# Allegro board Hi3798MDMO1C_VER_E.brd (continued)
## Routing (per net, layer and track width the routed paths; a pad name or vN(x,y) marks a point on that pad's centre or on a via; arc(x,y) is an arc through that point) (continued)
VDD_AUDIO: length 12.2
  TOP w0.254: U5.9 100.93,67.09 R48.1 C158.1 101.45,64.66 C320.1 101.41,63.4 R179.2 100.57,63.37 100.01,63.93 R66.2
ADAC_VOUTL: length 29.9
  TOP w0.254: C350.2 97.18,61.51 96.88,61.81 R50.1 96.47,61.69 96.03,61.25 78.02,61.25 76.21,59.43 76.21,54.48 75.48,53.75 74.9,53.75 U1.B22
ADAC_VOUTR: length 20.9
  TOP w0.254: C351.1 87.99,64.67 R183.1 87.9,63.7 83.27,63.7 82.68,63.11 78.16,63.11 75.17,60.12 75.17,55.78 U1.A22
AUDIO_L: length 9.1
  BOTTOM w0.254: J34.2 100.95,76.83 99.83,75.71 C339.1 99.83,70.7 99.83,70.7 R72.2
AUDIO_R: length 10.8
  BOTTOM w0.254: R74.1 92.58,70.06 92.58,71.11 ; 92.58,71.11 C140.1 ; 92.58,71.11 92.58,75.6 91.35,76.82 89.33,76.82 89.32,76.83 J34.1
CORE_CTRL: length 9.8
  TOP w0.127: U1.H22 74.42,49.6 74.99,50.17 76.69,50.17 77.43,50.92 79.51,50.92 81.14,52.55 81.14,53.44 80.94,53.65 R23.2
CPU_CTRL: length 10.2
  TOP w0.127: U1.H23 75.36,49.29 76.56,49.29 77.5,50.23 80.38,50.23 82.04,51.9 82.04,54.07 R21.2
CVBS: length 49.3
  TOP w0.254: C80.1 108.78,71.08 L6.1 107.89,71.1 C79.1 R9.1 106.98,69.54 106.81,69.36 106.81,64.02 102.89,60.1 78.63,60.1 77.35,58.82 77.35,53.95 75.24,51.83 U1.E23
CVBS_OUT: length 14.4
  TOP w0.254: v1(114.78,70.38) 113.81,70.38 D9.3 112.29,71.9 C17.1 C80.2 108.78,71.9 L6.2
  BOTTOM w0.254: J34.3 117.84,73.44 v1(114.78,70.38)
DDR_ADDR0: length 98
  TOP w0.127: U1.AC14 68.02,37.07 67.94,36.99 67.94,22.81 59.68,14.55 30.21,14.55 20.46,24.3 20.46,42.65 25.81,48 v1(25.94,48) RN2.1
  BOTTOM w0.127: RN2.1 v1(25.94,48)
DDR_ADDR0_A: length 18.5
  TOP w0.127: U3.N3 41.01,47.56 41.42,47.96 41.42,50.49 40.19,51.71 31.91,51.71 28.2,48 RN2.8
DDR_ADDR0_B: length 24.2
  TOP w0.127: U6.N3 41.01,31.25 41.42,31.66 41.42,33.98 40.06,35.34 v1(40.06,35.42)
  BOTTOM w0.127: v1(40.06,35.42) 39.97,35.42 39.67,35.72 39.67,36.85 35.26,41.26 35.26,42.75 29.52,48.49 28.77,48.49 28.29,48 RN11.1
DDR_ADDR1: length 66.5
  TOP w0.127: v1(26.37,32.98) 26.45,33.07 26.5,33.07 26.57,33.15 RN4.3 ; U1.Y10 v2(65.22,40.23)
  BOTTOM w0.127: v2(65.22,40.23) 65.06,40.23 64.57,39.75 64.57,31.72 52.6,19.75 30.75,19.75 24.31,26.19 24.31,30.96 26.34,32.98 v1(26.37,32.98) 26.53,33.15 RN4.3
DDR_ADDR1_A: length 17.3
  TOP w0.127: U3.P7 40.21,44.01 39.83,43.64 39.83,43.36 39.5,43.03 39.2,43.03 38.97,42.8 38.97,42.27 38.76,42.06 37.54,42.06 28.62,33.15 RN4.6
DDR_ADDR1_B: length 17.6
  TOP w0.127: v1(36.05,25.73) 38.61,25.73 38.97,26.09 38.97,26.36 39.17,26.57 39.55,26.57 39.86,26.87 39.86,27.23 40.21,27.58 U6.P7
  BOTTOM w0.127: RN13.3 28.25,33.15 30.84,30.56 30.84,28.81 33.49,26.16 35.62,26.16 v1(36.05,25.73)
DDR_ADDR2: length 95.4
  TOP w0.127: U1.W14 v2(68.42,40.24) ; RN1.4 v1(26.47,42.67)
  BOTTOM w0.127: v2(68.42,40.24) 68.42,40.04 68.83,39.64 68.83,27.93 55.9,15 28.41,15 19.56,23.85 19.56,37.57 24.67,42.67 v1(26.47,42.67) RN1.4
DDR_ADDR2_A: length 14.4
  TOP w0.127: U3.P3 39.87,47.09 37.3,47.09 36.89,47.5 33.57,47.5 28.75,42.67 RN1.5
DDR_ADDR2_B: length 18.7
  TOP w0.127: U6.P3 39.87,30.68 38.3,30.68 37.32,31.66 37.32,31.68 36.55,32.45 v1(36.55,32.63)
  BOTTOM w0.127: v1(36.55,32.63) 36.34,32.84 36.34,34.43 31.12,39.64 31.12,40.48 28.93,42.67 RN9.4
DDR_ADDR3: length 96.5
  TOP w0.127: U1.AB14 68.02,37.92 67.68,37.58 67.68,37.29 67.69,37.28 67.69,23.09 59.53,14.93 30.37,14.93 20.84,24.46 20.84,42.49 25.85,47.5 v1(26.47,47.5) RN2.2
  BOTTOM w0.127: RN2.2 v1(26.47,47.5)
DDR_ADDR3_A: length 17
  TOP w0.127: U3.N2 41.01,48.45 40.61,48.85 40.61,50.63 39.91,51.33 32.06,51.33 28.61,47.88 28.61,47.7 28.4,47.5 RN2.7
DDR_ADDR3_B: length 22.7
  TOP w0.127: U6.N2 41.01,32.02 40.62,32.41 40.62,34.17 v1(39.33,35.46)
  BOTTOM w0.127: v1(39.33,35.46) 39.33,36.66 34.88,41.11 34.88,42.59 29.36,48.11 28.84,48.11 28.61,47.88 28.61,47.62 28.48,47.5 RN11.2
DDR_ADDR4: length 64.4
  TOP w0.127: U1.W10 64.82,40.63 v2(64.42,40.24) ; RN4.4 26.85,32.64 26.42,32.2 v1(26.42,32.2)
  BOTTOM w0.127: RN4.4 26.83,32.64 26.42,32.23 v1(26.42,32.2) 26.21,32.2 26.04,32.03 26.02,32.03 24.69,30.7 24.69,26.35 30.91,20.13 52.44,20.13 64.27,31.96 64.27,40.08 v2(64.42,40.24)
DDR_ADDR4_A: length 17.2
  TOP w0.127: RN4.5 28.66,32.64 37.7,41.68 39.56,41.68 39.81,41.93 39.81,42.83 40.21,43.23 U3.P8
DDR_ADDR4_B: length 17.4
  TOP w0.127: v1(35.29,25.73) 35.75,25.26 36.39,25.26 36.5,25.36 39.01,25.36 39.03,25.34 39.36,25.34 39.75,25.74 39.75,26.08 39.75,26.08 39.75,26.26 40.21,26.72 U6.P8
  BOTTOM w0.127: v1(35.29,25.73) 33.38,25.73 30.46,28.65 30.46,30.42 28.24,32.64 RN13.4
DDR_ADDR5: length 107.3
  TOP w0.127: RN2.3 v1(25.94,46.99) ; U1.Y16 v2(70.02,40.23)
  BOTTOM w0.127: RN2.3 v1(25.94,46.99) 24.87,46.99 17.92,40.04 17.92,21.4 26,13.32 56.64,13.32 70.42,27.1 70.42,39.65 70.02,40.04 v2(70.02,40.23)
DDR_ADDR5_A: length 15.1
  TOP w0.127: RN2.6 28.99,46.99 32.39,50.39 39.26,50.39 39.81,49.84 39.81,48.63 U3.P2
DDR_ADDR5_B: length 20.6
  TOP w0.127: U6.P2 39.81,32.23 39.81,33.46 39.33,33.95 v2(39.33,34.39)
  BOTTOM w0.127: v2(39.33,34.39) 38.64,35.08 38.64,36.16 34.02,40.77 34.02,41.96 28.99,46.99 RN11.3
DDR_ADDR6: length 70.3
  TOP w0.102: 65.1,37.01 65.09,37.03 65.09,37.89 65.15,37.95 65.15,38.7 U1.AA10
  TOP w0.127: 65.1,37.01 65.1,26.14 56.86,17.89 33.14,17.89 24.65,26.38 24.65,32.24 26.16,33.75 v1(26.21,33.75) 26.31,33.65 RN4.2
  BOTTOM w0.127: v1(26.21,33.75) 26.32,33.64 27.06,33.64 RN4.2
DDR_ADDR6_A: length 15.6
  TOP w0.127: U3.R8 39.12,43.43 38.7,43.01 37.29,43.01 28.56,34.28 28.56,33.78 28.43,33.65 RN4.7
DDR_ADDR6_B: length 15.4
  TOP w0.127: v1(35.13,27.02) 35.55,26.61 36.21,26.61 36.28,26.67 38.74,26.67 39.1,27.02 U6.R8
  BOTTOM w0.127: RN13.2 28.96,33.65 31.69,30.92 31.69,29.22 33.89,27.02 v1(35.13,27.02)
DDR_ADDR7: length 103.8
  TOP w0.127: RN2.4 v1(26.47,46.48) ; U1.AA16 v2(70.02,39.43)
  BOTTOM w0.127: v2(70.02,39.43) 70.02,27.25 56.48,13.71 26.15,13.71 18.3,21.56 18.3,39.86 24.92,46.48 v1(26.47,46.48) RN2.4
DDR_ADDR7_A: length 13.9
  TOP w0.127: U3.R2 39.41,48.45 39,48.87 39,49.39 38.37,50.01 32.57,50.01 29.04,46.48 RN2.5
DDR_ADDR7_B: length 19.8
  TOP w0.127: v2(38.56,34.43) 38.64,34.35 38.64,34 39.02,33.62 39.02,32.44 39.41,32.05 U6.R2
  BOTTOM w0.127: v2(38.56,34.43) 38.56,34.52 38.26,34.83 38.26,36 33.64,40.61 33.64,41.79 28.95,46.48 RN11.4
DDR_ADDR8: length 71.5
  TOP w0.102: 65.48,36.94 65.29,37.13 65.29,37.7 65.62,38.03 U1.AB11
  TOP w0.127: RN4.1 26.81,34.16 26.5,34.47 v1(26.47,34.47) 26.28,34.47 24.27,32.47 24.27,26.22 32.98,17.51 57.02,17.51 65.48,25.98 65.48,36.94
  BOTTOM w0.127: RN4.1 26.78,34.16 v1(26.47,34.47)
DDR_ADDR8_A: length 14.5
  TOP w0.127: RN4.8 28.11,34.37 37.1,43.36 38.54,43.36 U3.T8
DDR_ADDR8_B: length 14.4
  TOP w0.127: U6.T8 v1(35.95,27.02)
  BOTTOM w0.127: v1(35.95,27.02) 35.49,27.48 33.97,27.48 32.07,29.38 32.07,31.08 28.99,34.16 RN13.1
DDR_ADDR9: length 89.7
  TOP w0.102: 66.9,36.93 66.99,37.01 66.99,37.83 66.81,38.01 66.81,38.65 U1.AA12
  TOP w0.127: RN1.2 v1(26.47,43.69) 25.03,43.69 22.11,40.77 22.11,25.09 31.31,15.89 58.67,15.89 66.9,24.13 66.9,36.93
  BOTTOM w0.127: RN1.2 v1(26.47,43.69)
DDR_ADDR9_A: length 14.1
  TOP w0.127: RN1.7 28.43,43.69 28.61,43.87 28.61,44.28 33.07,48.74 37.07,48.74 37.27,48.54 37.75,48.54 38.49,47.8 38.84,47.8 39.21,47.43 U3.R3
DDR_ADDR9_B: length 18.7
  TOP w0.127: v2(37.8,33.07) 37.9,32.97 37.9,31.98 38.46,31.42 38.82,31.42 39.21,31.02 U6.R3
  BOTTOM w0.127: v2(37.8,33.07) 37.31,33.56 37.31,35.18 32.38,40.11 32.38,41.19 29.88,43.69 RN9.2
DDR_ADDR10: length 56.3
  TOP w0.127: U1.Y8 v2(63.62,39.44) ; RN6.3 26.5,29.72 v1(26.42,29.64)
  BOTTOM w0.127: RN8.6 26.52,29.72 26.45,29.64 v1(26.42,29.64) 25.53,28.75 25.53,26.79 30.45,21.87 36.26,21.87 36.68,22.3 52.8,22.3 63.68,33.18 63.68,39.38 v2(63.62,39.44)
DDR_ADDR10_A: length 22.3
  TOP w0.127: U3.L7 42.61,43.98 43.01,43.59 43.01,42.11 41.33,40.44 39.4,40.44 28.68,29.72 RN6.6
DDR_ADDR10_B: length 22.9
  TOP w0.127: U6.L7 42.62,27.82 42.96,27.48 42.96,24.74 41.43,23.22 v1(35.67,23.22)
  BOTTOM w0.127: RN8.3 28.43,29.72 28.56,29.59 28.56,29.01 28.38,28.83 28.38,27.56 32.38,23.56 34.38,23.56 34.5,23.67 35.21,23.67 v1(35.67,23.22)
DDR_ADDR11: length 75.1
  TOP w0.127: v1(26.47,36.22) 26.52,36.22 26.63,36.32 RN5.3 ; U1.Y11 v2(66.02,40.23)
  BOTTOM w0.127: v2(66.02,40.23) 66.02,40.08 65.79,39.85 65.79,30.23 54.05,18.48 30.11,18.48 23.01,25.58 23.01,33.35 25.88,36.22 v1(26.47,36.22) 26.58,36.32 RN5.3
DDR_ADDR11_A: length 14.8
  TOP w0.127: RN5.6 28.3,36.32 36.55,44.58 39.07,44.58 U3.R7
DDR_ADDR11_B: length 15.8
  TOP w0.127: U6.R7 39.07,28.17 35.44,28.17 v1(35.06,28.55)
  BOTTOM w0.127: v1(35.06,28.55) 35.03,28.55 34.4,29.18 33.92,29.18 33.31,29.79 33.31,31.6 28.59,36.32 RN10.3
DDR_ADDR12: length 61.4
  TOP w0.127: U1.AB9 64.2,38.06 64.2,37.74 64.36,37.58 64.36,27.39 55.83,18.86 34.01,18.86 25.92,26.95 25.92,29.88 v1(26.42,30.38) 26.58,30.22 RN6.2
  BOTTOM w0.127: RN8.7 26.58,30.22 v1(26.42,30.38)
DDR_ADDR12_A: length 20.9
  TOP w0.127: RN6.7 28.35,30.22 28.61,30.48 28.61,30.86 38.65,40.91 40.19,40.91 40.84,41.56 41.06,41.56 41.17,41.67 41.19,41.67 41.43,41.92 41.43,42.27 41.41,42.29 41.41,43.83 U3.N7
DDR_ADDR12_B: length 20
  TOP w0.127: U6.N7 41.01,27.58 41.41,27.18 41.41,25.52 41.41,25.52 41.41,25.5 41.13,25.22 40.75,25.22 39.78,24.26 36.2,24.26 35.84,23.89 35.4,23.89 v1(34.91,24.38)
  BOTTOM w0.127: RN8.2 28.66,30.22 29.22,29.67 29.22,28.04 32.81,24.45 34.84,24.45 v1(34.91,24.38)
DDR_ADDR13: length 96.9
  TOP w0.127: RN1.3 v1(25.92,43.18) ; U1.Y15 v2(69.22,39.44)
  BOTTOM w0.127: RN1.3 v1(25.92,43.18) 25.76,43.03 24.52,43.03 19.18,37.69 19.18,23.69 28.25,14.62 56.06,14.62 69.2,27.76 69.2,39.41 v2(69.22,39.44)
DDR_ADDR13_A: length 12.6
  TOP w0.127: U3.T3 37.51,47.43 37.07,47.88 33.41,47.88 28.71,43.18 RN1.6
DDR_ADDR13_B: length 17.1
  TOP w0.127: v1(37.29,32.37) 37.29,32.32 37.62,31.98 37.62,31.83 38.43,31.02 U6.T3
  BOTTOM w0.127: v1(37.29,32.37) 37.08,32.58 37.08,32.73 36.74,33.08 36.74,34.57 31.5,39.8 31.5,40.64 28.96,43.18 RN9.3
DDR_ADDR14: length 72.6
  TOP w0.127: v1(26.49,35.42) 26.49,35.45 26.85,35.81 RN5.4 ; U1.AA11 v2(65.22,39.44)
  BOTTOM w0.127: RN5.4 26.81,35.81 26.49,35.5 v1(26.49,35.42) 26.38,35.53 25.74,35.53 23.39,33.19 23.39,25.74 30.27,18.86 53.89,18.86 65.41,30.38 65.41,39.25 v2(65.22,39.44)
DDR_ADDR14_A: length 13.9
  TOP w0.127: RN5.5 28.33,35.81 36.75,44.23 U3.T7
DDR_ADDR14_B: length 14.8
  TOP w0.127: U6.T7 38.24,27.82 38.22,27.85 35.02,27.85 v1(34.35,28.52)
  BOTTOM w0.127: v1(34.35,28.52) 34.03,28.84 33.75,28.84 32.91,29.68 32.91,31.42 28.52,35.81 RN10.4
DDR_ADDR15: length 80.6
  TOP w0.127: U1.W12 v2(66.82,40.24) ; v1(26.47,37.47) 26.5,37.47 26.63,37.34 RN5.1
  BOTTOM w0.127: v2(66.82,40.24) 66.82,39.99 66.43,39.6 66.43,29.06 54.72,17.35 29.62,17.35 21.98,24.99 21.98,33.82 25.63,37.47 v1(26.47,37.47) 26.6,37.34 RN5.1
DDR_ADDR15_A: length 17.2
  TOP w0.127: U3.M7 41,45.05 35.82,45.05 28.16,37.39 RN5.8
DDR_ADDR15_B: length 18.4
  TOP w0.127: v1(35.13,29.54) 36.02,28.65 40.99,28.65 U6.M7
  BOTTOM w0.127: RN10.1 28.76,37.34 33.89,32.21 33.89,30.78 v1(35.13,29.54)
DDR_BA0: length 102.2
  TOP w0.127: RN7.4 26.7,49.78 v1(26.44,49.52) 26.34,49.42 25.96,49.42 19.57,43.03 19.57,23.86 29.47,13.96 60.38,13.96 68.9,22.48 68.9,36.99 68.82,37.07 U1.AC15
  BOTTOM w0.127: RN7.4 26.7,49.78 v1(26.44,49.52)
DDR_BA0_A: length 19.1
  TOP w0.127: RN7.5 28.71,49.78 31.58,52.65 40.95,52.65 42.22,51.38 42.22,48.64 U3.M2
DDR_BA0_B: length 24.9
  TOP w0.127: U6.M2 42.2,32.22 42.2,34.59 v1(40.52,36.27)
  BOTTOM w0.127: RN14.4 29.8,49.78 36.12,43.47 36.12,41.6 40.29,37.44 40.29,36.5 v1(40.52,36.27)
DDR_BA1: length 64.6
  TOP w0.127: RN6.1 26.76,30.73 v1(26.39,31.1) 25.54,30.26 25.54,26.79 33.85,18.48 55.99,18.48 64.59,27.08 64.59,37.67 64.47,37.8 64.47,38.39 64.02,38.83 U1.AA9
  BOTTOM w0.127: v1(26.39,31.1) 26.76,30.73 RN8.8
DDR_BA1_A: length 19
  TOP w0.127: RN6.8 28.11,30.9 38.37,41.16 39.95,41.16 40,41.21 40.61,41.82 40.61,42.76 41.01,43.16 U3.N8
DDR_BA1_B: length 18.2
  TOP w0.127: U6.N8 41.01,26.76 40.61,26.36 40.61,25.86 40.62,25.86 40.62,25.49 40.39,25.26 40.39,25.26 39.65,24.52 35.81,24.52 v1(35.67,24.38)
  BOTTOM w0.127: RN8.1 28.66,30.73 29.6,29.79 29.6,28.2 32.97,24.83 35.22,24.83 v1(35.67,24.38)
DDR_BA2: length 82
  TOP w0.127: U1.Y12 66.02,39.43 66.02,25.12 57.83,16.93 32.28,16.93 23.38,25.83 23.38,37.77 25.97,40.36 v1(26.45,40.36) 26.47,40.38 RN3.2
  BOTTOM w0.127: v1(26.45,40.36) 26.47,40.38 RN3.2
DDR_BA2_A: length 17
  TOP w0.127: RN3.7 28.47,40.38 28.68,40.6 28.68,40.86 34.11,46.29 41.22,46.29 41.81,46.88 U3.M3
DDR_BA2_B: length 20
  TOP w0.127: U6.M3 41.81,30.61 41.15,29.95 37.41,29.95 36,31.35 v1(36,31.47)
  BOTTOM w0.127: RN12.2 29.32,40.38 29.87,39.84 29.87,39.15 35.34,33.68 35.34,32.13 v1(36,31.47)
DDR_CASN: length 86
  TOP w0.127: RN3.4 26.91,39.37 26.47,38.93 v1(26.47,38.85) ; v2(67.62,39.44) 68.02,39.83 U1.Y14
  BOTTOM w0.127: RN3.4 26.91,39.37 26.47,38.93 v1(26.47,38.85) 25.17,38.85 20.83,34.52 20.83,24.46 29.02,16.27 55.27,16.27 67.62,28.63 v2(67.62,39.44)
DDR_CASN_A: length 19.1
  TOP w0.127: RN3.5 28.94,39.37 35.07,45.5 42.34,45.5 42.98,46.15 42.98,47 U3.K3
DDR_CASN_B: length 21.7
  TOP w0.127: v1(35.36,30.53) 35.47,30.53 36.81,29.18 42.07,29.18 43.03,30.15 43.03,30.65 U6.K3
  BOTTOM w0.127: RN12.4 28.16,39.14 34.43,32.87 34.43,31.04 34.94,30.53 v1(35.36,30.53)
DDR_CKE: length 55.1
  TOP w0.127: U1.W9 64.02,40.63 v2(63.62,40.24) ; v1(26.47,28.88) 26.8,29.21 RN6.4
  BOTTOM w0.127: RN8.5 26.8,29.21 v1(26.47,28.88) 25.94,28.35 25.94,26.92 30.61,22.26 36.03,22.26 36.46,22.68 52.65,22.68 63.2,33.23 R38.2 63.2,39.81 v2(63.62,40.24)
DDR_CKE_A: length 21.2
  TOP w0.127: RN6.5 28.7,29.21 39.67,40.18 41.61,40.18 43.07,41.64 43.41,41.98 U3.K9
DDR_CKE_B: length 21.6
  TOP w0.127: U6.K9 43.41,24.63 41.48,22.71 35.41,22.71 v1(34.91,23.22)
  BOTTOM w0.127: RN8.4 28.11,29.01 28,28.89 28,27.4 32.22,23.17 34.42,23.17 34.46,23.22 v1(34.91,23.22)
DDR_CLK0N: length 68
  TOP w0.152: v2(44.78,39.44) 44.63,39.3 44.61,39.3 44.24,38.93 43.71,38.93 43.16,39.48 40.15,39.48 31.71,31.03 31.71,22.47 34.4,19.78 55.25,19.78 55.6,20.13 62.49,27.02 R35.1
  TOP w0.165: U3.K7 43.41,44.47 v2(43.9,44.96)
  BOTTOM w0.165: v2(44.78,39.44) 44.83,39.5 44.83,39.97 R11.1 44.61,40.65 44.01,41.25 44.01,42.7 44.57,43.26 44.57,44.21 43.9,44.88 v2(43.9,44.96)
DDR_CLK0P: length 68
  TOP w0.152: v2(45.45,39.42) 45.02,38.99 44.73,38.99 44.36,38.62 43.59,38.62 43.04,39.17 40.28,39.17 32.01,30.91 32.01,22.6 34.52,20.09 55.16,20.09 55.48,20.41 62.13,27.05 R18.1
  TOP w0.165: v2(44.56,44.91) 44.21,44.56 U3.J7
  BOTTOM w0.165: v2(44.56,44.91) 44.56,44.86 44.89,44.53 44.89,43.13 44.33,42.57 44.33,41.39 45.16,40.56 45.16,40.39 45.35,40.19 45.48,40.19 ; 45.48,40.19 R15.2 ; 45.48,40.19 45.12,39.83 45.12,39.7 45.4,39.42 v2(45.45,39.42)
DDR_CLK1N: length 63.8
  TOP w0.152: v1(44.43,36.96) 44.31,36.84 43.96,36.84 42.52,38.28 40.63,38.28 32.95,30.6 32.95,22.97 34.85,21.07 53.94,21.07 59.68,26.81 60,26.81 R37.1 ; v2(43.66,28.81) 43.69,28.78 43.69,28.1 U6.K7
  BOTTOM w0.152: v1(44.43,36.96) 44.56,36.96 44.76,36.76 44.76,36.27 43.74,35.25 43.74,31.39 43.1,30.75 43.1,29.76 R16.1 43.44,29.08 43.44,29.03 v2(43.66,28.81)
DDR_CLK1P: length 63.5
  TOP w0.152: U6.J7 44.17,27.87 44.17,28.52 v2(44.46,28.81) ; R36.1 59.41,26.97 53.81,21.37 34.98,21.37 33.26,23.1 33.26,30.47 40.76,37.98 42.37,37.98 43.83,36.52 44.63,36.52 45.07,36.96 v1(45.25,36.96)
  BOTTOM w0.152: v2(44.46,28.81) 44.26,28.81 44.02,29.04 R17.2 43.93,29.41 43.41,29.94 43.41,30.62 44.05,31.26 44.05,35.12 45.07,36.14 45.07,36.77 v1(45.25,36.96)
DDR_CSN: length 81.7
  TOP w0.127: U1.AC12 66.42,37.19 66.36,37.13 66.36,24.92 57.99,16.55 32.12,16.55 23,25.67 23,37.93 26.07,41 26.32,41 v1(26.44,41.11) 26.66,40.89 RN3.1
  BOTTOM w0.127: RN3.1 26.66,40.89 v1(26.44,41.11)
DDR_CSN_A: length 17.8
  TOP w0.127: U3.L2 42.37,48.23 41.99,47.85 41.74,47.85 41.38,47.5 41.38,47 41,46.62 33.9,46.62 28.17,40.89 RN3.8
DDR_CSN_B: length 21.2
  TOP w0.127: v1(36.73,31.28) 36.73,31.17 37.68,30.22 40.9,30.22 41.41,30.73 41.41,31.24 41.54,31.37 41.94,31.37 42.4,31.82 U6.L2
  BOTTOM w0.127: v1(36.73,31.28) 36.73,31.35 35.72,32.36 35.72,33.84 30.25,39.3 30.25,39.97 29.32,40.89 RN12.1
DDR_DM0: length 14.4
  TOP w0.127: U1.K4 v2(59.62,47.43) ; U3.E7 v2(47.81,44.63)
  BOTTOM w0.127: v2(59.62,47.43) 59.6,47.46 57.63,47.46 57.23,47.06 53.21,47.06 52.52,46.37 48.99,46.37 47.81,45.19 v2(47.81,44.63)
DDR_DM1: length 13.7
  TOP w0.127: U3.D3 48.68,46.96 v2(49.51,46.96) ; U1.L5 v2(60.42,47.44)
  BOTTOM w0.127: v2(60.42,47.44) 60.02,47.84 57.38,47.84 56.92,47.39 53.09,47.39 52.38,46.68 49.79,46.68 v2(49.51,46.96)
DDR_DM2: length 17.2
  TOP w0.127: U6.E7 v2(47.41,28.37) ; U1.AA1 v2(57.22,38.64)
  BOTTOM w0.127: v2(57.22,38.64) 56.63,38.04 56.63,36.81 54.25,34.44 54.25,32.15 52.25,30.15 49.74,30.15 47.96,28.37 v2(47.41,28.37)
DDR_DM3: length 16.2
  TOP w0.127: U1.Y2 v2(58.02,39.44) ; U6.D3 48.61,30.62 v2(49.41,30.62)
  BOTTOM w0.127: v2(49.41,30.62) 52.12,30.62 53.92,32.43 53.92,34.69 54.65,35.41 56.31,37.07 56.31,38.32 57.07,39.08 57.67,39.08 v2(58.02,39.44)
DDR_DQ0: length 17.1
  TOP w0.127: U3.E3 v2(47.01,47.83) ; U1.H4 v2(59.62,49.83)
  BOTTOM w0.127: v2(47.01,47.83) 47.01,48.12 47.81,48.92 47.81,50.93 48.14,51.26 51.6,51.26 53.03,49.83 v2(59.62,49.83)
DDR_DQ1: length 15.1
  TOP w0.127: U1.N1 57.25,45.43 57.11,45.29 54.85,45.29 50.86,41.3 47.52,41.3 47,41.81 47,43.63 46.61,44.02 U3.F7
DDR_DQ2: length 14
  TOP w0.127: U1.H1 57.56,49.49 53.99,49.49 52.03,51.46 48.37,51.46 47.01,50.1 47.01,48.63 U3.F2
DDR_DQ3: length 17.1
  TOP w0.127: U3.F8 46.15,42.98 46.15,41.88 46.42,41.62 46.42,41.62 47.12,40.92 50.84,40.92 54.97,45.05 58.81,45.05 U1.P3
DDR_DQ4: length 19.7
  TOP w0.127: U3.H3 45.41,47.83 v2(46.21,47.83) ; U1.H5 v2(60.42,49.83)
  BOTTOM w0.127: v2(46.21,47.83) 47.43,49.05 47.43,51.1 47.99,51.66 51.68,51.66 53.1,50.24 60.02,50.24 v2(60.42,49.83)
DDR_DQ5: length 19.1
  TOP w0.127: U3.H8 44.62,43.04 44.62,41.93 46.76,39.79 51.31,39.79 55.58,44.06 58.15,44.06 58.26,44.18 58.88,44.18 U1.R3
DDR_DQ6: length 15.8
  TOP w0.127: U1.H2 58.03,49.82 54.17,49.82 52.2,51.8 48.12,51.8 46.21,49.89 46.21,48.63 U3.G2
DDR_DQ7: length 18.4
  TOP w0.127: U1.P2 58.27,44.63 57.93,44.29 55.49,44.29 51.21,40.02 46.91,40.02 45.44,41.48 45.44,43.65 45.01,44.09 U3.H7
DDR_DQ8: length 13
  TOP w0.127: U1.M4 v2(59.62,46.63) ; v2(48.61,44.63) U3.D7
  BOTTOM w0.127: v2(48.61,44.63) 49.56,45.58 52.73,45.58 53.16,46.01 57.18,46.01 57.57,46.41 59.06,46.41 59.29,46.63 v2(59.62,46.63)
DDR_DQ9: length 13.5
  TOP w0.127: U1.K2 58.25,47.83 57.89,48.2 52.62,48.2 52.08,48.74 52.08,49.76 51.49,50.34 49.77,50.34 49.42,49.99 49.42,47.84 U3.C3
DDR_DQ10: length 15
  TOP w0.127: U3.C8 v2(48.61,43.03) ; U1.M5 v2(60.42,46.63)
  BOTTOM w0.127: v2(48.61,43.03) 48.61,43.27 49.1,43.76 49.1,44.53 49.81,45.23 52.86,45.23 53.26,45.63 57.23,45.63 57.63,46.04 59.19,46.04 59.39,46.24 60.03,46.24 v2(60.42,46.63)
DDR_DQ11: length 14.5
  TOP w0.127: U1.J3 58.81,48.22 58.22,48.22 57.96,48.48 52.78,48.48 52.41,48.85 52.41,49.81 51.57,50.65 49.36,50.65 48.62,49.91 48.62,48.63 U3.C2
DDR_DQ12: length 10.1
  TOP w0.127: U3.A7 52.03,44.23 52.3,43.96 v2(52.4,43.96) ; U1.N4 v2(59.62,45.03)
  BOTTOM w0.127: v2(52.4,43.96) 52.42,43.96 53.41,44.95 59.14,44.95 59.22,45.03 v2(59.62,45.03)
DDR_DQ13: length 9.9
  TOP w0.127: U3.A2 v2(51.18,48.23) ; U1.J4 v2(59.62,49.03)
  BOTTOM w0.127: v2(51.18,48.23) 51.36,48.42 56.56,48.42 57.17,49.03 v2(59.62,49.03)
DDR_DQ14: length 12.1
  TOP w0.127: U3.B8 49.99,43.43 50.35,43.79 51.28,43.79 51.3,43.81 v2(51.72,43.81) ; U1.P4 v2(60.42,45.03)
  BOTTOM w0.127: v2(60.42,45.03) 60.23,45.03 59.82,44.63 59.46,44.63 53.76,44.63 52.59,43.46 52.07,43.46 v2(51.72,43.81)
DDR_DQ15: length 11
  TOP w0.127: U1.J5 v2(60.42,49.03) ; v2(51.18,47.49) 51.11,47.43 U3.A3
  BOTTOM w0.127: v2(51.18,47.49) 51.72,48.04 56.75,48.04 57.36,48.64 60.03,48.64 v2(60.42,49.03)
DDR_DQ16: length 21.5
  TOP w0.127: U6.E3 v2(47.01,31.42) ; U1.T5 v2(60.42,43.44)
  BOTTOM w0.127: v2(60.42,43.44) 55.66,43.44 54.2,41.98 54.2,40.73 48.13,34.66 48.13,32.95 47.01,31.82 v2(47.01,31.42)
DDR_DQ17: length 27
  TOP w0.127: U6.F7 46.98,27.46 46.98,25.37 48.41,23.93 52.08,23.93 60.25,32.11 60.25,37.84 60.43,38.02 60.43,38.38 60.82,38.77 U1.AA5
DDR_DQ18: length 17.9
  TOP w0.127: U6.F2 47.01,32.23 47.01,33.52 53.42,39.92 53.42,40.56 56.23,43.38 57.81,43.38 57.89,43.3 58.16,43.3 U1.T2
DDR_DQ19: length 27.1
  TOP w0.127: U6.F8 46.23,26.65 46.23,24.9 46.8,24.33 47.28,24.33 48.06,23.55 52.24,23.55 60.48,31.8 60.48,37.66 60.82,38 U1.AB5
DDR_DQ20: length 23.5
  TOP w0.127: v2(46.21,31.42) 45.41,31.42 U6.H3 ; U1.R5 v2(60.42,44.23)
  BOTTOM w0.127: v2(46.21,31.42) 47.78,33 47.78,34.87 53.77,40.86 53.77,42.41 55.15,43.78 59.97,43.78 v2(60.42,44.23)
DDR_DQ21: length 30.5
  TOP w0.127: U1.AC6 61.62,31.11 52.81,22.3 47.17,22.3 44.4,25.07 44.4,25.93 44.55,26.08 44.55,26.57 U6.H8
DDR_DQ22: length 19.4
  TOP w0.127: U6.G2 46.21,32.23 46.21,33.31 53.14,40.23 53.14,40.6 56.14,43.61 58.16,43.61 58.28,43.49 58.55,43.49 58.88,43.16 58.88,43.16 59.01,43.03 U1.T3
DDR_DQ23: length 31.5
  TOP w0.127: U1.AA6 61.24,38.65 61.24,31.27 52.65,22.68 47.33,22.68 45.36,24.64 45.36,27.47 U6.H7
DDR_DQ24: length 23.7
  TOP w0.127: U6.D7 48.21,27.61 48.63,27.2 48.63,25.39 49.11,24.91 51.78,24.91 59.81,32.93 59.81,37.9 59.62,38.09 59.62,38.63 U1.AA4
DDR_DQ25: length 15.6
  TOP w0.127: U6.C3 49.42,31.43 49.42,33.66 54.56,38.8 54.56,40.53 56.27,42.23 U1.U1
DDR_DQ26: length 20.1
  TOP w0.127: U1.AB3 59.22,38.23 59.22,37.98 59.56,37.64 59.56,37.58 59.56,33.22 51.54,25.2 50.28,25.2 49.43,26.06 49.43,26.3 49.01,26.72 U6.C8
DDR_DQ27: length 17.2
  TOP w0.127: U1.U3 58.82,42.64 56.31,42.64 54.27,40.6 54.27,39.04 49.22,33.99 48.61,33.38 48.61,32.22 U6.C2
DDR_DQ28: length 13.9
  TOP w0.127: U6.A7 52.37,27.82 58.42,33.88 U1.AC2
DDR_DQ29: length 17.5
  TOP w0.127: U6.A2 50.63,31.85 51.44,31.85 v2(51.51,31.92) ; U1.T4 v2(59.62,42.63)
  BOTTOM w0.127: v2(51.51,31.92) 51.51,31.92 51.73,32.14 52.12,32.53 52.12,34.97 55.37,38.22 55.37,41.67 56.34,42.63 v2(59.62,42.63)
DDR_DQ30: length 16.5
  TOP w0.127: U1.AB2 58.42,37.98 58.81,37.59 58.81,33.71 52.53,27.42 50.42,27.42 50.02,27.02 U6.B8
DDR_DQ31: length 18.7
  TOP w0.127: U6.A3 v2(51.01,31.42) ; U1.U4 v2(60.42,42.63)
  BOTTOM w0.127: v2(51.01,31.42) 51.75,31.42 51.95,31.62 52.45,32.12 52.45,34.76 53.19,35.5 55.75,38.06 55.75,41.39 56.59,42.23 60.02,42.23 v2(60.42,42.63)
DDR_DQS0N: length 13.4
  TOP w0.152: U3.G3 46.11,47.43 46.31,47.24 46.31,46.42 46.79,45.94 52.55,45.94 53.75,47.13 57.52,47.13 U1.L1
DDR_DQS0P: length 13.5
  TOP w0.152: U3.F3 46.61,46.55 46.91,46.24 52.43,46.24 53.62,47.44 57.78,47.44 58.18,47.03 U1.L2
DDR_DQS1N: length 10.6
  TOP w0.152: U3.B7 49.81,44.57 50.32,45.08 53.37,45.08 54.2,45.91 56.24,45.91 56.44,46.12 58.03,46.12 58.27,45.87 58.86,45.87 U1.M3
DDR_DQS1P: length 10.6
  TOP w0.152: U1.M2 58.24,46.42 56.31,46.42 56.11,46.22 54.08,46.22 53.25,45.39 50.2,45.39 49.5,44.69 49.5,44.41 49.3,44.21 49.04,44.21 U3.C7
DDR_DQS2N: length 22.1
  TOP w0.152: U6.G3 46.09,31.02 46.25,30.87 46.25,30.07 46.67,29.65 50.99,29.65 53.33,31.99 53.33,35.47 55.58,37.71 55.58,40.25 56.59,41.26 58.25,41.26 U1.V2
DDR_DQS2P: length 22.2
  TOP w0.152: U6.F3 46.61,30.15 46.81,29.95 50.87,29.95 53.03,32.11 53.03,35.59 55.27,37.84 55.27,40.38 56.46,41.57 57.96,41.57 58.22,41.82 58.6,41.82 58.98,41.43 U1.V3
DDR_DQS3N: length 17.8
  TOP w0.152: U6.B7 49.81,28.28 50.32,28.79 51.84,28.79 56.46,33.42 56.46,39.54 57.19,40.26 57.81,40.26 58.19,40.63 U1.W2
DDR_DQS3P: length 17.8
  TOP w0.152: U6.C7 49.09,27.75 49.24,27.75 49.44,27.95 49.44,28.36 50.18,29.1 51.71,29.1 56.16,33.54 56.16,39.66 57.06,40.57 57.06,40.57 57.13,40.63 U1.W1
DDR_ODT: length 105
  TOP w0.127: RN7.3 v1(26.42,50.29) 26.3,50.29 19.19,43.19 19.19,23.7 29.31,13.58 60.54,13.58 69.16,22.21 69.16,37.6 68.82,37.94 U1.AB15
  BOTTOM w0.127: v1(26.42,50.29) RN7.3
DDR_ODT_A: length 19
  TOP w0.127: RN7.6 28.66,50.29 31.4,53.03 41.08,53.03 42.55,51.56 42.55,49.89 U3.K1
DDR_ODT_B: length 25.1
  TOP w0.127: U6.K1 42.55,33.48 42.55,34.85 41.33,36.07 41.33,36.26 v1(41.33,36.26)
  BOTTOM w0.127: RN14.3 29.93,50.29 36.5,43.72 36.5,41.76 40.67,37.58 40.67,36.86 41.27,36.26 v1(41.33,36.26)
DDR_PLL: length 10
  TOP w0.254: U1.T12 v2(66.02,43.43) 65.95,43.51 64.83,43.51 64.76,43.44 64.31,43.44 64.26,43.48 63.33,43.48 63.11,43.7 v2(63.11,44.9)
  TOP w0.305: v2(63.11,44.9) 63.22,45.02 U1.N8
  BOTTOM w0.381: C264.1 v2(66.02,43.43) ; C270.1 62.82,44.62 v2(63.11,44.9) 62.96,45.05 C11.1 62.96,46.11 62.63,46.44 62.63,47.05 LB7.1
DDR_RASN: length 109.3
  TOP w0.127: RN7.1 v1(26.42,51.31) 26,51.31 18.29,43.6 18.29,23.3 28.59,13 61.29,13 69.98,21.69 69.98,37.87 U1.AB16
  BOTTOM w0.127: RN7.1 v1(26.42,51.31)
DDR_RASN_A: length 22.1
  TOP w0.127: RN7.8 28.38,51.31 31.04,53.96 41.47,53.96 43.82,51.61 43.82,48.08 44.21,47.69 U3.J3
DDR_RASN_B: length 28.4
  TOP w0.127: v1(41.33,37.24) 41.84,37.24 43.8,35.28 43.8,31.75 44.21,31.33 U6.J3
  BOTTOM w0.127: RN14.1 30.16,51.31 37.37,44.09 37.37,42.11 41.33,38.15 v1(41.33,37.24)
DDR_RESETN: length 91.1
  TOP w0.127: RN1.1 v1(25.92,44.19) 25,44.19 21.73,40.93 21.73,24.93 31.15,15.51 58.83,15.51 67.18,23.87 67.18,36.9 67.21,36.92 67.21,37.75 67.22,37.77 U1.AB13
  BOTTOM w0.127: RN1.1 v1(25.92,44.19)
DDR_RESETN_A: length 15.3
  TOP w0.127: RN1.8 28.16,44.38 32.9,49.12 37.24,49.12 v2(37.42,48.95) 37.9,48.95 U3.T2
  BOTTOM w0.127: R60.2 38.16,50.19 C313.1 37.27,49.09 v2(37.42,48.95)
DDR_RESETN_B: length 20.7
  TOP w0.127: v2(38,33.77) 38,33.66 38.22,33.44 38.22,32.22 U6.T2
  BOTTOM w0.127: C314.1 R76.2 38.22,32.97 38.22,33.44 38,33.66 v2(38,33.77) 37.73,34.04 37.73,35.31 32.77,40.26 32.77,41.35 29.93,44.19 RN9.1
DDR_VREF_CA_A: length 4.6
  TOP w0.305: v2(42.21,43.03) U3.M8
  BOTTOM w0.381: R51.2 C207.2 41.1,44.47 R55.1 41.1,44.09 41.59,43.61 C289.1 41.76,43.03 v2(42.21,43.03)
DDR_VREF_CA_B: length 5
  TOP w0.203: v2(42.21,25.73) 42.21,26.62 U6.M8
  BOTTOM w0.381: v2(42.21,25.73) 42.42,25.52 C310.1 R107.1 42.78,24.23 R103.2 C222.2
DDR_VREF_DQ_A: length 4.4
  TOP w0.305: v2(45.04,50.1) 45.01,50.07 U3.H1
  BOTTOM w0.381: v2(45.04,50.1) 45.04,50.1 45.04,50.65 C271.1 R75.1 R54.2 C208.2
DDR_VREF_DQ_B: length 4.6
  TOP w0.305: U6.H1 v2(45.01,33.73)
  BOTTOM w0.381: R84.1 R78.2 C223.2 C308.1 45.01,34.36 v2(45.01,33.73)
DDR_WEN: length 88.8
  TOP w0.127: U1.Y13 v2(67.62,40.23) ; v1(26.42,39.56) 26.73,39.88 RN3.3
  BOTTOM w0.127: RN3.3 26.73,39.88 v1(26.42,39.56) 25.37,39.56 20.45,34.65 20.45,24.3 28.86,15.89 55.42,15.89 68.03,28.5 68.03,39.6 67.62,40 v2(67.62,40.23)
DDR_WEN_A: length 18.2
  TOP w0.127: U3.L3 42.61,46.37 42.08,45.83 34.87,45.83 28.91,39.88 RN3.6
DDR_WEN_B: length 21
  TOP w0.127: U6.L3 42.61,30.26 41.82,29.46 37.07,29.46 35.29,31.24 v1(35.16,31.24)
  BOTTOM w0.127: v1(35.16,31.24) 34.75,31.65 34.75,33.07 28.68,39.14 28.68,39.67 28.48,39.88 RN12.3
FE_1V1: length 1.4
  TOP w0.305: v2(64.42,49.84) 64.82,50.23 U1.G10
  BOTTOM w0.305: v2(64.42,49.84) 64.27,49.68 C248.1
FE_3V3: length 0.6
  TOP w0.305: U1.E5 v2(60.42,52.24)
HDMI_TX0N: length 67.6
  TOP w0.152: J26.9 23.97,76.06 23.98,76.06 23.98,75.12 24.09,75.01 U24.9 U24.2 24.09,72.69 23.98,72.58 23.98,68 26.44,65.55 32.17,65.55 37.96,59.76 51.07,59.76 54.52,63.21 63.3,63.21 70.05,56.45 70.05,53.29 69.82,53.05 69.82,52.83 U1.D16
HDMI_TX0P: length 67.5
  TOP w0.152: J26.7 22.98,77.83 22.98,76.44 23.71,75.7 23.71,75.13 23.59,75.01 U24.10 U24.1 23.59,72.69 23.68,72.59 23.68,67.88 26.31,65.24 32.04,65.24 37.84,59.45 51.2,59.45 54.65,62.91 63.17,62.91 67.28,58.79 67.28,58.63 67.28,58.46 67.48,58.27 67.65,58.27 67.81,58.27 68.35,57.72 68.35,57.6 68.35,57.47 68.55,57.27 68.68,57.27 68.81,57.27 69,57.07 69,56.95 69,56.82 69.2,56.62 69.33,56.62 69.45,56.62 69.75,56.33 69.75,53.56 U1.C16
HDMI_TX1N: length 66.5
  TOP w0.152: U1.B15 69.19,54.6 69.19,55.67 64.31,60.58 62.86,62.04 55.04,62.04 51.64,58.64 37.41,58.64 31.67,64.38 25.76,64.38 22.33,67.81 22.33,72.3 22.33,72.31 22.33,72.62 22.41,72.69 U23.5 U23.6 22.41,75.01 22.3,75.12 22.3,75.43 22.47,75.6 J26.6
HDMI_TX1P: length 66.3
  TOP w0.152: J26.4 21.47,76 22.02,75.45 22.02,75.12 21.91,75.01 U23.7 U23.4 21.91,72.69 22.03,72.58 22.03,72.43 22.02,72.43 22.02,67.68 25.63,64.07 31.55,64.07 37.29,58.33 51.77,58.33 55.17,61.74 62.73,61.74 65.1,59.35 65.1,59.05 65.29,58.85 65.6,58.85 66.5,57.94 66.5,57.69 66.7,57.49 66.83,57.49 66.95,57.49 67.36,57.08 67.36,56.83 67.56,56.63 67.8,56.63 68,56.44 68,56.19 68.2,55.99 68.44,55.99 68.88,55.55 68.88,55.1 U1.A15
HDMI_TX2N: length 68.1
  TOP w0.152: J26.3 20.97,75.94 20.81,75.78 20.81,75.11 20.91,75.01 U23.9 U23.2 20.91,72.82 20.8,72.71 20.8,66.86 24.53,63.13 31.27,63.13 36.88,57.52 52.26,57.52 55.64,60.9 62.36,60.9 68.4,54.85 68.4,53.82 U1.C14
HDMI_TX2P: length 68
  TOP w0.152: U1.B14 68.1,54.31 68.1,54.73 67.75,55.07 67.47,55.07 67.28,55.27 67.28,55.55 67.08,55.74 66.8,55.74 66.6,55.94 66.6,56.22 66.41,56.42 66.13,56.42 65.93,56.62 65.93,56.9 65.73,57.09 65.45,57.09 65.25,57.29 65.25,57.57 62.23,60.59 55.76,60.59 52.39,57.22 36.75,57.22 31.14,62.83 24.4,62.83 20.5,66.73 20.5,72.68 20.41,72.77 U23.1 U23.10 20.41,75.01 20.53,75.13 20.53,75.85 19.97,76.41 J26.1
HDMI_TX_1V1: length 1.1
  TOP w0.305: U1.G15 68.82,50.23 v2(68.42,49.83) 68.02,50.23 U1.G14
HDMI_TX_3V3: length 0.6
  TOP w0.381: U1.E15 68.42,52.23 v2(68.42,52.23)
HDMI_TX_CEC: length 66.2
  TOP w0.127: v1(37.47,63.1) 32.99,67.58 30.4,67.58 29.93,68.06 29.93,68.52 30.32,68.91 R268.2 30.32,69.49 U4.3 28.77,70.82 26.95,72.64 26.95,75.56 25.97,76.53 J26.13 ; v1(57.12,65.14) 57.51,65.14 57.83,65.46 64.83,65.46 72.14,58.16 72.14,56.36 71.36,55.57 71.36,53.94 71.22,53.8 U1.C18
  BOTTOM w0.127: v1(57.12,65.14) 56.21,65.14 56.02,65.33 41.08,65.33 38.86,63.1 v1(37.47,63.1)
HDMI_TX_HOTPLUG: length 70
  TOP w0.127: U1.B19 72.4,54.61 72.4,55.4 73.28,56.28 73.28,58.54 64.92,66.9 56.89,66.9 v1(56.49,66.5) ; v1(38.07,64.81) 37.08,64.81 33.43,68.46 C149.1 R8.2 32.94,69.6 32.82,69.72 U4.4 35.91,70.82 36.26,71.17 36.26,74.88 35.23,75.91 29.59,75.91 28.97,76.53 J26.19
  BOTTOM w0.127: v1(56.49,66.5) 56.05,66.5 55.7,66.16 40.2,66.16 38.86,64.81 v1(38.07,64.81)
HDMI_TX_SCL: length 65.9
  TOP w0.127: J26.15 26.97,76.13 27.34,75.76 27.34,74.87 28.18,74.03 R186.1 30.33,73.54 30.32,73.53 U4.1 31.2,72.72 31.42,72.49 31.42,69.87 32.59,68.7 32.59,68.14 32.89,67.83 33.12,67.83 37.34,63.62 v1(38.07,63.62) ; U1.D18 71.61,53.02 71.61,55.51 72.52,56.41 72.52,58.28 64.87,65.93 57.73,65.93 57.4,65.6 v1(56.49,65.6)
  BOTTOM w0.127: v1(56.49,65.6) 40.84,65.6 38.86,63.62 v1(38.07,63.62)
HDMI_TX_SDA: length 68.9
  TOP w0.127: U1.A19 72.02,55.4 72.87,56.25 72.87,58.42 64.87,66.41 57.46,66.41 v1(57.1,66.05) ; v1(37.38,64.2) 37.29,64.2 33.4,68.09 33.05,68.09 32.84,68.29 32.84,68.95 31.78,70.02 31.78,72.55 31.94,72.72 U4.6 33.7,72.72 33.91,72.93 33.91,73.7 34.21,74.01 R187.1 34.75,74.5 34.61,74.64 28.36,74.64 27.84,75.15 27.84,75.84 27.47,76.2 J26.16
  BOTTOM w0.127: v1(57.1,66.05) 56.28,66.05 56.13,65.9 40.64,65.9 38.94,64.2 v1(37.38,64.2)
HDMI_TXCN: length 65.3
  TOP w0.152: U1.B17 70.62,54.43 70.82,54.63 70.82,55 70.84,55.02 70.84,57.5 63.93,64.4 54.09,64.4 50.69,61 38.33,61 32.61,66.72 27.8,66.72 25.48,69.04 25.48,72.68 25.59,72.8 U24.5 U24.6 25.59,75.01 25.48,75.12 25.48,77.83 J26.12
HDMI_TXCP: length 65.3
  TOP w0.152: J26.10 24.47,76.63 25.21,75.89 25.21,75.13 25.09,75.01 U24.7 U24.4 25.09,72.82 25.17,72.74 25.17,68.91 27.68,66.41 32.48,66.41 38.2,60.7 50.81,60.7 54.22,64.1 63.81,64.1 66.76,61.15 66.76,60.89 66.96,60.69 67.21,60.69 67.41,60.5 67.41,60.24 67.61,60.04 67.86,60.04 68.6,59.31 68.6,59 68.8,58.8 69.1,58.8 69.78,58.13 69.78,57.82 69.97,57.63 70.28,57.63 70.54,57.37 70.54,55.15 U1.A17
IR_IN: length 83.8
  TOP w0.127: R140.1 117.46,15.3 117.2,15.55 117.2,16.47 117.09,16.58 117.09,18.15 115.57,19.67 v1(113.79,19.67) ; U1.Y21 74.02,39.43 74.02,38.86 74.3,38.58 74.58,38.58 74.8,38.36 74.8,37.33 75.37,36.76 75.37,23.4 v1(75.72,23.05) ; v1(109.6,19.69) 109.35,19.69 108.59,18.93 108.59,18.81 102.07,12.3 77.5,12.3 v2(77.14,12.65)
  TOP w0.254: D3.1 116.44,10.76 115.79,11.42 J3.3 115.79,12.69 117.84,14.74 R140.1
  BOTTOM w0.127: v2(77.14,12.65) 77.14,14.2 78.14,15.2 78.14,20.62 76.25,22.51 76.25,22.52 v1(75.72,23.05) ; v1(109.6,19.69) 109.62,19.66 113.78,19.66 v1(113.79,19.67)
LED0_BASE: length 37.9
  TOP w0.127: U1.B2 58.02,53.84 55.48,53.84 54.42,52.78 43.93,52.78 41.79,54.93 39.31,54.93 39.19,55.06 v2(39.19,55.29) ; v1(39.19,62.04) 38.8,62.42 38.8,70.13 38.56,70.37 R26.2 R67.2
  BOTTOM w0.127: v2(39.19,55.29) v1(39.19,62.04)
LED0_LINK_ACT: length 17.2
  TOP w0.127: v1(50.95,62.25) 50.95,62.86 52.97,64.88 52.97,65.5 R30.2 53.52,66.06 R79.2 ; U1.B1 56.54,54.23 v2(56.12,54.65)
  BOTTOM w0.127: v1(50.95,62.25) 50.95,61.77 56.12,56.59 v2(56.12,54.65)
LED_GREEN: length 74.1
  TOP w0.127: R3.2 R22.1 R77.1 115.07,17.21 114.95,17.34 114.95,18.4 v1(114.63,18.71) ; U1.AB22 74.07,37.88 74.07,37.1 74.86,36.3 74.86,22 75.41,21.45 75.85,21.45 v1(76.4,20.91) ; v2(75.73,12.46) 76.17,12.02 102.33,12.02 v1(109.04,18.74)
  BOTTOM w0.127: v1(109.04,18.74) 114.61,18.74 v1(114.63,18.71) ; v1(76.4,20.91) 77.04,20.26 77.04,15.63 75.73,14.32 v2(75.73,12.46)
LED_GREEN_1: length 10.3
  TOP w0.254: LED1.3 113.77,9.9 112.74,10.94 112.27,10.94 111.79,11.42 J3.1 111.74,11.77 Q1.3 111.74,17.32 R2.2
LED_RED: length 51.5
  TOP w0.127: v1(96.37,11.57) 96.2,11.73 75.2,11.73 v2(74.28,12.66) ; v1(75.66,21.92) 75.12,22.46 75.12,36.56 74.42,37.25 U1.AC22
  BOTTOM w0.127: v2(74.28,12.66) 74.28,14.35 75.66,15.73 v1(75.66,21.92) ; v1(96.37,11.57) 96.43,11.51 R49.1
  BOTTOM w0.254: R49.1 R31.1 R65.2
LED_RED_1: length 26.9
  TOP w0.254: J3.5 120.22,11.29 120.22,8.96 119.51,8.24 109.17,8.24 108.69,8.72 LED1.1
  BOTTOM w0.254: LED1.1 107.6,9.5 107.43,9.67 105.01,9.67 103.82,10.87 R34.2 101.55,14.07 Q2.3
MUTE_CTRL: length 30.3
  TOP w0.127: v1(83.01,62.27) 83.06,62.32 83.44,62.32 83.84,62.72 93.73,62.72 94.02,63.01 R90.1 ; U1.C19 72.41,53.82 73.06,53.82 73.65,54.42 73.65,55.71 74.2,56.26 74.2,60.75 v1(75.26,61.81)
  BOTTOM w0.127: v1(75.26,61.81) 82.54,61.81 v1(83.01,62.27)
NF_ALE_EMMC_PWREN: length 24.6
  TOP w0.102: 76.66,44.55 76.62,44.52 74.21,44.52 73.75,44.97 73.28,44.97 U1.N20
  TOP w0.127: 76.66,44.55 77.09,44.98 95.21,44.98 95.66,44.53 U19.17
NF_CLE: length 24.3
  TOP w0.102: 77.3,45.24 76.9,45.24 76.4,44.74 74.32,44.74 U1.N21
  TOP w0.127: 77.3,45.24 95.51,45.24 96.16,44.59 U19.16
NF_CSN0_EMMC_CMD: length 38.8
  TOP w0.102: 77.43,45.49 76.77,45.49 76.29,45.01 74.85,45.01 U1.N22
  TOP w0.127: v2(99.41,42.36) 99.41,42.39 99.66,42.64 U19.9 99.66,44.35 98.52,45.49 77.43,45.49
  TOP w0.254: U22.W5 99.16,35.77 98.88,35.48 v2(98.85,35.48)
  BOTTOM w0.127: v2(99.41,42.36) 99.07,42.02 99.07,39.46 97.5,37.89 97.5,37.28 ; 97.5,37.28 97.49,37.26 R212.2 ; 97.5,37.28 97.5,35.5 97.96,35.05 98.42,35.05 v2(98.85,35.48)
NF_DQ0_EMMC_D0: length 51.9
  TOP w0.127: v2(96.62,27.56) 96.03,27.56 94.16,25.69 U19.29 94.16,23.16 92.96,21.96 92.3,21.96 R189.2 91.54,21.73 91.04,22.23 91.04,38.46 85.02,44.48 77.43,44.48 76.7,43.74 75.32,43.74 U1.R23 ; v2(100.58,29.56) 100.58,29.77 100.16,30.18 U22.H3
  BOTTOM w0.127: v2(100.58,29.56) 99.74,30.4 98.16,30.4 97.43,29.67 97.43,29.09 96.62,28.28 v2(96.62,27.56)
NF_DQ1_EMMC_D1: length 54.1
  TOP w0.102: U1.R22 74.81,43.44 76.81,43.44 76.95,43.58
  TOP w0.127: U22.H4 99.66,29.59 v2(99.69,29.56) ; 76.95,43.58 77.59,44.22 84.89,44.22 90.79,38.33 90.79,20.68 91.17,20.29 92.44,20.29 92.84,20.69 92.84,21.33 93.24,21.73 R12.2 94.66,22.79 U19.30 94.66,25.42 95.9,26.66 v2(96.65,26.66)
  BOTTOM w0.127: v2(99.69,29.56) 99.23,30.02 98.28,30.02 97.78,29.51 97.78,28.98 97.16,28.36 97.16,27.17 v2(96.65,26.66)
NF_DQ2_EMMC_D2: length 54.9
  TOP w0.102: 77.09,43.33 77,43.24 74.22,43.24 U1.R21
  TOP w0.127: v2(98.83,29.54) 98.83,29.84 99.16,30.18 U22.H5 ; 77.09,43.33 77.73,43.97 84.77,43.97 90.53,38.2 90.53,20.45 91.11,19.87 94.04,19.87 94.36,20.18 94.36,21.33 94.77,21.73 R29.2 95.16,21.77 U19.31 95.16,25.29 96.02,26.15 97.07,26.15 v2(97.58,26.66)
  BOTTOM w0.127: v2(98.83,29.54) 98.16,28.87 97.58,28.29 v2(97.58,26.66)
NF_DQ3_EMMC_D3: length 58.5
  TOP w0.089: U22.J2 100.41,30.75 100.41,30.34
  TOP w0.102: U1.T21 77.17,43.03 77.26,43.12
  TOP w0.127: 100.41,30.34 101.01,29.74 101.01,28.86 99.95,27.8 99.44,27.8 99.06,27.42 98.55,27.42 98.17,27.04 98.17,26.53 97.54,25.9 96.4,25.9 95.66,25.15 U19.32 95.66,22.77 96.39,22.04 R58.2 96.04,21.73 95.76,21.45 95.76,20.18 95.18,19.61 90.94,19.61 90.28,20.28 90.28,38.08 84.64,43.71 77.85,43.71 77.26,43.12
NF_DQ4_EMMC_D4: length 58.5
  TOP w0.089: 99.91,30.15 99.91,30.75 U22.J3
  TOP w0.102: 75.98,42.77 75.94,42.81 74.6,42.81 74.4,42.62 73.24,42.62 U1.T20
  TOP w0.127: v2(99.69,28.31) 99.69,28.29 100.12,28.72 100.12,29.82 99.91,30.03 99.91,30.15 ; v2(99.54,26.41) 99.95,25.99 99.95,25.15 100.16,24.94 U19.41 100.16,22.8 99.6,22.24 98.31,22.24 R176.2 97.3,21.73 97.12,21.54 97.12,20.12 96.35,19.35 90.74,19.35 89.3,20.79 89.3,37.78 84.31,42.77 75.98,42.77
  BOTTOM w0.127: v2(99.54,26.41) 99.69,26.56 v2(99.69,28.31)
NF_DQ5_EMMC_D5: length 58.6
  TOP w0.089: U22.J4 99.41,30.75 99.41,30.2
  TOP w0.102: 75.69,42.58 74.77,42.58 U1.U22
  TOP w0.127: v2(98.81,28.69) 99.26,29.14 99.26,29.82 99.41,29.97 99.41,30.2 ; v2(100.43,26.41) 100.43,25.3 100.66,25.06 U19.42 100.66,22.91 99.49,21.73 R177.2 98.57,21.73 98.35,21.51 98.35,19.83 97.61,19.09 90.62,19.09 89.05,20.66 89.05,37.66 84.18,42.52 75.76,42.52 75.69,42.58
  BOTTOM w0.127: v2(98.81,28.69) 98.93,28.82 99.82,28.82 100.43,28.22 v2(100.43,26.41)
NF_DQ6_EMMC_D6: length 59
  TOP w0.089: U22.J5 98.91,30.75 98.91,30.33
  TOP w0.127: U1.U23 75.25,42.27 84.06,42.27 88.79,37.53 88.79,20.54 90.49,18.84 98.25,18.84 99.71,20.3 99.71,21.16 100.28,21.73 R188.2 101.16,22.55 U19.43 v2(101.16,26.02) ; v2(98.79,27.86) 98.34,28.31 98.34,29.77 98.91,30.33
  BOTTOM w0.127: v2(101.16,26.02) 100.91,25.77 99.47,25.77 99.09,26.15 99.09,27.56 v2(98.79,27.86)
NF_DQ7_EMMC_D7_BOOT_SEL0: length 62.7
  TOP w0.089: U22.J6 98.41,30.76 98.41,30.34 98.27,30.2
  TOP w0.127: v2(98.03,27.82) 97.82,28.04 97.82,29.75 98.27,30.2 ; U1.U21 73.98,41.87 75.49,41.87 75.63,42.01 83.93,42.01 88.54,37.4 88.54,20.41 90.36,18.58 98.37,18.58 99.59,19.8 100.61,19.8 100.91,20.11 100.91,21.53 101.11,21.73 R202.2 101.61,22.44 101.66,22.49 U19.44 v2(101.66,25.39)
  BOTTOM w0.127: v2(101.66,25.39) 99.44,25.39 98.81,26.02 98.81,26.69 98.68,26.81 R33.1 98.3,27.56 v2(98.03,27.82)
NF_RDY0_EMMC_RST: length 44.2
  TOP w0.127: U1.M21 75.79,46.23 76.3,46.75 79.22,46.75 79.74,47.27 99.41,47.27 100.66,46.01 U19.7 100.66,42.48 v2(100.91,42.23)
  TOP w0.254: v2(99.69,34.77) 99.45,35 U22.U5
  BOTTOM w0.127: v2(100.91,42.23) 103.23,39.92 103.23,35.35 102.65,34.77 R203.2 101.34,34.67 C115.1 99.79,34.67 v2(99.69,34.77)
NF_REN_EMMC_CLK: length 34
  TOP w0.127: R68.1 79.27,45.91 79.74,46.38 98.9,46.38 100.16,45.12 U19.8 v2(100.16,42.26)
  TOP w0.254: U22.W6 98.66,36 98.17,35.51 v2(98.16,35.51)
  BOTTOM w0.127: v2(100.16,42.26) 99.45,41.54 99.45,39.39 97.8,37.74 97.8,35.87 v2(98.16,35.51)
NF_WEN_EMMC_DET: length 23.7
  TOP w0.127: U19.18 95.16,44.42 94.86,44.73 77.17,44.73 76.58,44.14 v2(76.45,44.14) 75.6,44.14 75.5,44.23 74.03,44.23 U1.P21
  BOTTOM w0.127: R56.2 76.59,44.27 v2(76.45,44.14)
NF_WP: length 3.1
  TOP w0.127: v2(94.66,42.38) U19.19
  BOTTOM w0.127: R215.2 R89.1 v2(94.66,42.38)
PWR_OFF/ON: length 5.8
  TOP w0.127: U1.J23 76.64,48.63 77.6,49.6 v2(78.32,49.6)
  BOTTOM w0.127: v2(78.32,49.6) 78.88,50.16 78.88,50.56 R40.1 R41.1
RECOVERY: length 47.4
  TOP w0.127: v1(73.43,61.36) 73.41,61.36 73.23,61.53 73.23,61.53 v1(71.83,62.93) ; U1.J22 74.05,49.01 74.05,49.7 74.25,49.91 74.25,50.33 74.66,50.74 75.96,50.74 77.59,52.36 78.61,52.36 79.42,53.18 79.42,54.28 79.41,54.28 79.41,57.84 v1(79.57,58)
  TOP w0.254: S1.2 67.21,82.29 R25.2 C38.2 67.21,80.21 v1(67.21,80.2)
  BOTTOM w0.127: v1(73.43,61.36) 73.43,61.34 74.32,60.45 77.12,60.45 v1(79.57,58) ; v1(71.83,62.93) 71.45,63.31 71.45,63.31 70.18,64.59 70.18,69.92 71.63,71.36 71.63,73.4 70.18,74.84 70.18,77.67 67.65,80.2 v1(67.21,80.2)
RF0: length 8.8
  TOP w0.457: L1.2 7.59,11.73 C89.1 arc(8.01,11.81) 8.35,12.04 arc(8.59,12.31) 8.8,12.61 arc(9.2,13.48) 9.34,14.43 U7.3
RF1: length 3.9
  TOP w0.457: U2.7 6.44,18.39 arc(7.02,17.61) 7.36,16.69 arc(7.42,16.34) C56.1 7.43,15.97 L7.2
RFF0: length 2.3
  TOP w0.457: J9.1 4.77,11.73 C88.1 4.78,11.73 L1.1
RFF1: length 2.2
  TOP w0.457: L7.1 C50.1 4.52,15.98 J8.1
RX+_PHY0: length 24.1
  TOP w0.152: v1(48.42,55.3) 48.92,54.8 53.42,54.8 55.87,57.26 59.59,57.26 60.27,56.59 60.27,55.8 60.68,55.39 60.68,53.81 60.45,53.59 60.45,53 U1.D5
  BOTTOM w0.152: v1(48.42,55.3) 48.65,55.53 48.65,55.73 48.49,55.9 46.53,55.9 46.19,56.24 46.19,56.54 46.1,56.63 U8.6 U8.3 46.1,58.16 46.74,58.79 R63.1
RX-_PHY0: length 24.2
  TOP w0.152: v1(49.21,55.3) 49.41,55.11 53.29,55.11 55.75,57.57 57.19,57.57 57.34,57.72 57.34,57.93 57.49,58.08 57.79,58.08 57.95,57.93 57.95,57.72 58.1,57.57 58.4,57.57 58.56,57.72 58.56,57.93 58.71,58.08 59.01,58.08 59.17,57.93 59.17,57.72 59.32,57.57 59.68,57.57 60.55,56.7 60.55,55.92 60.96,55.51 60.96,53.57 U1.C5
  BOTTOM w0.152: v1(49.21,55.3) 48.96,55.56 48.96,55.86 48.62,56.2 46.66,56.2 46.49,56.37 46.49,56.52 46.61,56.63 U8.5 U8.4 46.61,58.16 47.6,59.15 R64.1
SPDIF_OUT_BOOT_SEL1: length 1.6
  TOP w0.127: U1.A20 v2(73.23,55.44)
  BOTTOM w0.254: v2(73.23,55.44) 72.94,55.16 R39.1
STANDBY_PWROFF: length 224.9
  TOP w0.127: R73.1 94.61,55.44 v1(94.29,55.11) ; v1(101.8,57.32) 102.05,57.08 106.74,57.08 108.31,55.51 108.31,48.87 111.33,45.85 111.33,40.72 108.31,37.71 108.31,26.94 104.48,23.1 104.48,22.21 99.91,17.64 90.3,17.64 85.62,22.32 v1(85.62,23.13) 86.19,23.7 v2(86.19,26.55) 86.19,33.29 85.49,34 83.74,34 83.32,34.43 R88.1 83.05,34.84 80.76,34.84 80.14,35.46 78.79,35.46 77.19,37.06 76.4,37.06 U1.AB23 ; R98.1 20.85,49.37 v2(20.84,49.35) ; v1(75.04,20.66) 75.35,20.34 78.21,17.48 79.5,17.48 80.36,18.34 81.66,18.34 82.73,19.41 v1(82.73,20.26) ; R47.1 13.3,45.8 v1(12.95,45.46) ; v2(16.64,42.18) 16.43,41.97 16.43,33.7 15.52,32.78 15.52,31.92 16.89,30.55 16.89,22.89 27.69,12.09 61.71,12.09 68.7,19.08 v1(69.51,19.08)
  BOTTOM w0.127: v1(69.51,19.08) 71.08,20.66 v1(75.04,20.66) ; R5.1 85.73,26.57 85.75,26.55 v2(86.19,26.55) ; v1(101.8,57.32) 100.03,55.55 94.73,55.55 v1(94.29,55.11) ; v1(85.62,23.13) 82.75,20.26 v1(82.73,20.26) ; v2(20.84,49.35) 20.84,48.06 18.23,45.46 v1(12.95,45.46) 12.95,44.95 13.08,44.82 15.66,44.82 16.64,43.84 v2(16.64,42.18)
TX+_PHY0: length 22.3
  TOP w0.114: U1.B4 59.68,54.57 59.68,55.24 59.07,55.86 58.95,55.86
  TOP w0.152: v1(44.89,55.3) 45.14,55.06 45.14,54.39 45.85,53.69 53.97,53.69 56.15,55.86 58.95,55.86
  BOTTOM w0.152: v1(44.89,55.3) 45.16,55.57 45.16,56.71 45.08,56.79 U8.8 U8.1 45.08,58.64 R59.1
TX-_PHY0: length 22.2
  TOP w0.114: U1.A4 60.02,55.26 59.12,56.16
  TOP w0.152: v1(45.69,55.3) 45.44,55.06 45.44,54.52 45.97,53.99 53.85,53.99 56.02,56.16 56.6,56.16 56.75,56.31 56.75,56.43 56.91,56.58 57.21,56.58 57.36,56.43 57.36,56.31 57.52,56.16 57.82,56.16 57.97,56.31 57.97,56.43 58.13,56.58 58.43,56.58 58.58,56.43 58.58,56.31 58.74,56.16 59.12,56.16
  BOTTOM w0.152: v1(45.69,55.3) 45.47,55.52 45.47,56.58 45.59,56.71 U8.7 U8.2 45.59,59.02 R62.1
UART0_RXD: length 34.7
  TOP w0.127: U1.AA22 74.61,39.03 75,39.42 75.34,39.42 75.89,38.87 75.89,38.51 76.84,37.57 77.4,37.57 78.96,36 80.48,36 81.12,35.37 85.96,35.37 87.45,33.87 87.45,22.11 87.71,21.85 v1(87.71,21.3) ; J18.2 84.97,18.69 85.01,18.73 R136.1
  BOTTOM w0.127: J18.2 84.97,18.04 87.71,20.79 v1(87.71,21.3)
UART0_TXD: length 33.9
  TOP w0.127: v1(87.13,21.8) 87.18,21.85 87.18,33.69 85.77,35.1 80.97,35.1 80.34,35.73 78.87,35.73 77.29,37.31 76.74,37.31 75.64,38.41 75.56,38.49 75.56,38.69 U1.AA23 ; J18.3 83.72,18.69 83.99,18.96 R135.2
  BOTTOM w0.127: J18.3 83.72,18.04 84.36,18.68 85.24,18.68 87.13,20.57 v1(87.13,21.8)
USB0_DM: length 31
  TOP w0.152: U1.A6 62.03,55.44 62.03,55.71 61.8,55.94 61.8,56.58
  TOP w0.203: J12.2 63.5,74.69 64.59,74.69 66.68,72.61 67.32,72.61 D5.1 67.87,72.63 68.27,72.63 C48.1 68.79,72.63 69.05,72.63 v1(69.18,72.76) ; 61.8,56.58 61.8,57.07 61.01,57.86 61.01,58.08 v1(61.21,58.28)
  BOTTOM w0.203: v1(69.18,72.76) 69.22,72.76 70.05,71.92 70.05,70.93 69.37,70.25 69.37,67.35 60.99,58.97 60.99,58.51 v1(61.21,58.28)
USB0_DP: length 31.1
  TOP w0.152: 61.47,56.57 61.47,55.73 61.26,55.52 61.26,54.59 U1.B6
  TOP w0.203: J12.3 63.31,74.36 64.46,74.36 66.54,72.28 67.33,72.28 D4.1 67.87,72.25 68.27,72.25 C42.1 68.79,72.25 68.96,72.25 v1(69.18,72.03) ; 61.47,56.57 61.47,56.94 60.68,57.72 60.68,57.95 v1(60.35,58.28)
  BOTTOM w0.203: v1(60.35,58.28) 60.66,58.59 60.66,59.11 69.04,67.49 69.04,70.38 69.72,71.07 69.72,71.79 69.48,72.03 v1(69.18,72.03)
USB01_1V1: length 0.6
  TOP w0.305: U1.G11 v2(66.02,49.84)
USB01_3V3: length 0.6
  TOP w0.305: U1.D7 v2(62.82,53.04)
USB1_DM: length 86.5
  TOP w0.203: v1(8.96,33.54) 8.96,33.47 10.86,31.57 U7.7 ; J2.4 8.87,37.49 9.63,38.24 9.63,39.04 10.16,39.57 10.51,39.92 12.55,39.92 17.58,44.95 25.73,53.1 25.73,60.52 27,61.79 30.81,61.79 36.27,56.33 52.77,56.33 56.15,59.71 61.77,59.71 63.25,58.23 63.25,55.74 62.42,54.92 U1.B7
  BOTTOM w0.203: v1(8.96,33.54) 9.16,33.34 9.46,33.34 9.75,33.63 9.75,34.46 8.87,35.34 J2.4
USB1_DP: length 86.4
  TOP w0.203: U1.C7 62.37,53.43 62.03,53.78 62.03,54.16 62.02,54.16 62.02,54.99 62.92,55.88 62.92,56.28 62.71,56.49 62.71,56.97 62.92,57.18 62.92,58.1 61.64,59.38 56.29,59.38 52.91,56 36.13,56 30.67,61.46 27.14,61.46 26.06,60.38 26.06,52.96 17.91,44.82 12.69,39.59 10.65,39.59 9.96,38.9 9.96,38.29 10.87,37.38 J2.3 ; v1(8.87,32.74) 8.72,32.74 7.36,31.38 U2.2
  BOTTOM w0.203: J2.3 10.87,35.25 10.08,34.46 10.08,33.49 9.6,33.01 9.14,33.01 v1(8.87,32.74)
USB3_DM: length 181.5
  TOP w0.203: U1.AC18 71.1,37.31 71.1,32.55 71.4,32.25 71.4,31.92 71.1,31.62 71.1,30.31 71.32,30.09 71.32,29.76 71.1,29.53 71.1,29.2 71.32,28.98 71.32,28.65 71.1,28.43 71.1,28.1 71.32,27.88 71.32,27.55 71.1,27.32 71.1,26.43 71.32,26.21 71.32,25.88 71.1,25.66 71.1,25.33 71.32,25.1 71.32,24.77 71.1,24.55 71.1,24.22 71.32,24 71.32,23.67 71.1,23.45 71.1,23.12 71.32,22.9 71.32,22.56 71.1,22.34 71.1,21.52 71.32,21.3 71.32,20.97 71.1,20.75 71.1,19.33 76.77,13.66 101.55,13.66 114,26.1 114,37.38 114.64,38.03 121.72,45.1 121.72,68.35 107.19,82.87 100.33,82.87 98.3,80.84 92.13,80.84 89.43,83.53 80.06,83.53 79.3,82.77 79.3,81.73 v1(79.5,81.52)
  BOTTOM w0.203: J28.2 75.31,71.23 76.15,72.08 78,72.08 79.2,73.27 79.2,81.22 v1(79.5,81.52)
USB3_DP: length 181.5
  TOP w0.203: U1.AB18 70.77,37.78 70.77,19.19 76.64,13.32 101.69,13.32 114.33,25.96 114.33,37.24 122.05,44.96 122.05,68.49 107.33,83.2 100.19,83.2 98.16,81.17 92.26,81.17 89.57,83.86 79.92,83.86 79.87,83.81 79.8,83.81 78.92,82.93 78.92,81.84 v1(78.6,81.52)
  BOTTOM w0.203: J28.3 75.31,72.58 75.49,72.41 77.87,72.41 78.87,73.41 78.87,81.26 v1(78.6,81.52)
USB3_RXN: length 169.2
  TOP w0.203: U1.AB20 72.82,38.04 73.48,37.38 73.48,36.68 73.89,36.27 73.89,20.44 78,16.32 100.37,16.32 110.85,26.8 110.85,38.19 118.86,46.21 118.86,67.46 113.13,73.19 105.59,73.19 104.6,72.2 84.23,72.2 77.57,78.86 69.99,78.86 69.52,78.39 69.52,78.12 69.72,77.91 69.72,77.58 69.52,77.38 69.52,77.05 69.72,76.85 69.72,76.52 69.52,76.31 69.52,76.14 71.75,73.91 72.52,73.91 72.67,74.06 72.67,75.28 72.98,75.58 J28.5
USB3_RXP: length 169.3
  TOP w0.203: U1.AC20 73.15,37.1 73.15,36.54 73.56,36.13 73.56,20.3 77.87,15.99 100.51,15.99 111.18,26.66 111.18,38.05 119.19,46.07 119.19,67.6 113.27,73.52 105.45,73.52 104.46,72.53 84.36,72.53 77.71,79.19 69.85,79.19 69.19,78.53 69.19,76 71.61,73.58 J28.6
USB3_TXN: length 186.3
  TOP w0.203: U1.AA19 72.02,38.91 72.2,38.74 72.2,36.59 72.42,36.38 72.42,36.05 72.2,35.83 72.2,35.5 72.42,35.28 72.42,34.95 72.2,34.73 72.2,34.41 72.49,34.11 72.49,33.53 72.72,33.3 72.72,32.97 72.49,32.74 72.49,32.41 72.72,32.19 72.72,31.86 72.49,31.63 72.49,31.25 72.72,31.03 72.72,30.7 72.49,30.47 72.49,30.14 72.72,29.91 72.72,29.58 72.49,29.36 72.49,27.97 72.72,27.74 72.72,27.41 72.49,27.18 72.49,26.85 72.72,26.63 72.72,26.3 72.49,26.07 72.49,24.92 72.72,24.69 72.72,24.36 72.49,24.13 72.49,23.8 72.72,23.58 72.72,23.25 72.49,23.02 72.49,21.84 72.72,21.61 72.72,21.28 72.49,21.06 72.49,19.94 77.45,14.98 78.02,14.98 78.24,15.2 78.57,15.2 78.8,14.98 79.13,14.98 79.36,15.2 79.69,15.2 79.91,14.98 80.24,14.98 80.47,15.2 80.8,15.2 81.02,14.98 100.98,14.98 112.55,26.54 112.55,37.94 120.36,45.75 120.36,67.83 113.58,74.62 105.23,74.62 104.22,73.6 84.79,73.6 78.05,80.33 69.45,80.33 67.68,78.56 67.68,76.07 70.48,73.27 70.48,71.24 69.39,70.14 68.36,70.14 67.82,69.6 67.82,68.95 68.02,68.75 68.35,68.75 C62.2
USB3_TXP: length 187.5
  TOP w0.203: C70.2 68.33,68.42 67.88,68.42 67.49,68.81 67.49,69.74 68.22,70.47 69.26,70.47 70.15,71.37 70.15,73.13 67.35,75.94 67.35,78.77 69.24,80.66 78.19,80.66 84.92,73.93 104.08,73.93 105.1,74.95 113.72,74.95 120.69,67.97 120.69,45.61 112.88,37.8 112.88,26.41 101.12,14.65 77.32,14.65 72.16,19.8 72.16,33.97 71.87,34.27 71.87,38.53 71.63,38.76 71.63,39.45 U1.Y19
USB03_VBUS: length 32.9
  TOP w1.143: J12.1 62.16,77.62 57.75,73.21 57.75,69.83 58.56,69.01 65.3,69.01 70.4,63.91 73.03,63.91 75.28,66.17 75.28,66.75 75.31,66.77 J28.1
  vias: v1(78.74,68.32) v1(78.74,67.55) v1(79.5,68.32) v1(79.5,67.55)
USB_BOOT: length 7.3
  TOP w0.127: U1.H21 73.62,49.68 74.01,50.08 74.01,50.52 74.5,51 75.88,51 78.32,53.44 R42.2
VDAC_3V3: length 2
  TOP w0.305: U1.G19 72.1,50.32 72.1,50.95 U1.F19 v2(72.42,51.44) U1.E20
XIN: length 11.1
  TOP w0.127: C364.1 80.28,37.42 81.11,38.25 82.69,38.25 83.53,37.41 X2.1
  TOP w0.203: C364.1 80.27,37.39 79.79,37.39 79.64,37.54 R1.2 79.03,37.54 78.51,38.06 78.13,38.06 77.73,38.46 77.73,39.22 76.31,40.63 U1.W23
XOUT: length 8.1
  TOP w0.203: U1.W22 74.81,41.02 76.54,41.02 78.11,39.45 78.11,38.58 78.24,38.46 78.52,38.46 R1.1 79.33,39.01 80.07,38.28 R14.1
$4N588: length 3.4
  TOP w0.254: R10.1 7.86,44.73 C84.1 7.86,46.52 R52.1 8.07,46.73 U15.5
$4N593: length 3.8
  TOP w0.127: R47.2 13.29,46.96 R6.2 12.25,46.96 C30.1 10.64,47.89 U15.1
$4N676: length 14.5
  TOP w0.127: C43.1 93.88,56.5 93.34,57.04 83.3,57.04 C71.1 82.12,55.86 R21.1
  TOP w0.508: R7.2 C43.1
$4N677: length 4.7
  TOP w0.508: U11.6 100.25,54.19 R99.2 100.25,55.64 R53.1 C76.1 R70.1
